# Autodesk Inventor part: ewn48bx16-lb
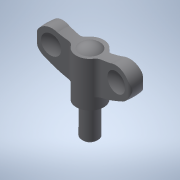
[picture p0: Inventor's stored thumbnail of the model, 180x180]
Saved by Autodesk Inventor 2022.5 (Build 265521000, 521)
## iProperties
Created: 2017-05
Part Number: ewn48bx16-lb
Material: 一般
Document SubType Name: Modeling
Designer: imaocorp
Density: 1 g/cm^3
Appearance: 既定
Author: imaocorp
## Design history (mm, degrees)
node "ewn48bx16-lb.x_t1"
node "ewn48bx16-lb"
node "Base1"
